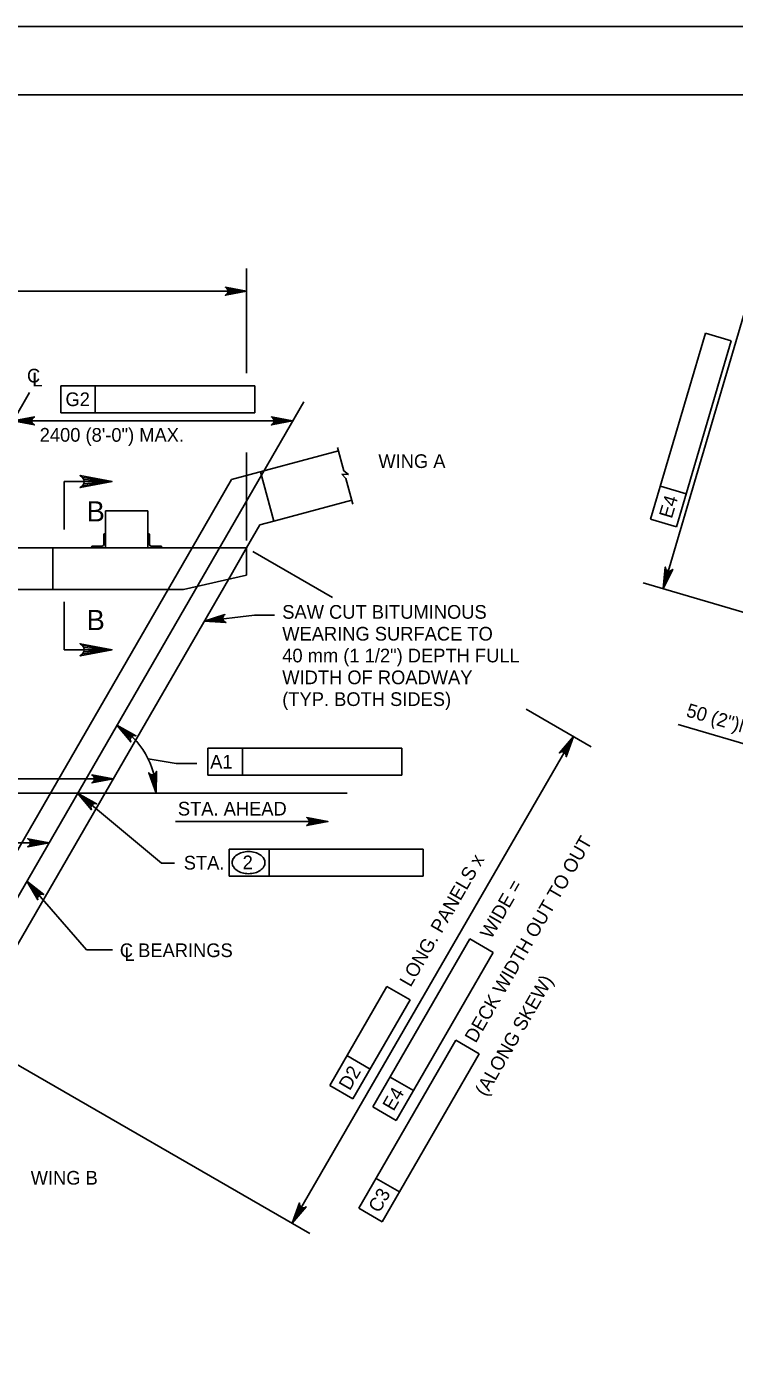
# Model space of a CAD drawing. Extents: x 638268 to 640277, y 295465 to 298435.
# Drawn here: x 639635.2 to 639790.3, y 298145.6 to 298435.5 of the extents above; entities that cross this region are included whole.
import ezdxf

# ---------------------------------------------------------------- set-up
doc = ezdxf.new("R2010")
doc.units = 0
for name, color, linetype in [('2', 7, 'Continuous'), ('3', 7, 'Continuous'), ('4', 7, 'Continuous'), ('PLT-BNDY', 7, 'Continuous')]:
    doc.layers.add(name, color=color, linetype=linetype)

msp = doc.modelspace()

# ---------------------------------------------------------------- linework, layer by layer
at = {"layer": '2'}
for p, q in [((639316.46, 298420.46), (640102.46, 298420.46)), ((639680.12, 298336.12), (639703.55, 298342.4)), ((639643.45, 298335.68), (639643.45, 298325.2)), ((639643.45, 298335.68), (639653.93, 298335.68)), ((639680.12, 298336.12), (639671.49, 298321.18)), ((639689.36, 298327.03), (639686.47, 298337.83)), ((639689.36, 298327.03), (639706.44, 298331.61)), ((639661.75, 298329.27), (639652.51, 298329.27)), ((639652.51, 298329.27), (639652.51, 298321.18)), ((639661.75, 298329.27), (639661.75, 298321.18)), ((639686.33, 298326.22), (639689.36, 298327.03)), ((639652.15, 298324.09), (639652.15, 298321.91)), ((639652.33, 298324.27), (639652.51, 298324.27)), ((639652.51, 298324.27), (639652.51, 298321.18)), ((639661.93, 298324.27), (639661.75, 298324.27)), ((639661.75, 298324.27), (639661.75, 298321.18)), ((639662.11, 298324.09), (639662.11, 298321.91)), ((639683.42, 298321.18), (639686.33, 298326.22)), ((639484.75, 298321.18), (639683.42, 298321.18)), ((639609.87, 298214.45), (639671.49, 298321.18)), ((639640.96, 298321.18), (639640.96, 298312.06)), ((639649.42, 298321.36), (639649.42, 298321.18)), ((639652.51, 298321.18), (639649.42, 298321.18)), ((639649.6, 298321.54), (639651.79, 298321.54)), ((639661.75, 298321.18), (639652.51, 298321.18)), ((639661.75, 298321.18), (639664.84, 298321.18)), ((639664.66, 298321.54), (639662.48, 298321.54)), ((639664.84, 298321.36), (639664.84, 298321.18)), ((639679.42, 298314.26), (639683.42, 298321.18)), ((639683.42, 298321.18), (639683.42, 298315.15)), ((639683.42, 298315.15), (639669.57, 298312.06)), ((639624.79, 298219.62), (639679.42, 298314.26)), ((639531.9, 298312.06), (639669.57, 298312.06)), ((639643.45, 298298.84), (639643.45, 298309.32)), ((639643.45, 298298.84), (639653.93, 298298.84))]:
    msp.add_line(p, q, dxfattribs=at)
for points in [[(639653.93, 298335.68), (639646.94, 298334.37), (639647.48, 298334.74), (639647.76, 298335.21), (639647.84, 298335.68), (639647.76, 298336.15), (639647.48, 298336.62), (639646.94, 298336.99), (639653.93, 298335.68), (639647.48, 298336.62), (639647.76, 298336.15), (639653.93, 298335.68), (639647.84, 298335.68), (639647.76, 298335.21), (639653.93, 298335.68), (639647.48, 298334.74)], [(639653.93, 298298.84), (639646.94, 298300.15), (639647.48, 298299.77), (639647.76, 298299.31), (639647.84, 298298.84), (639647.76, 298298.37), (639647.48, 298297.9), (639646.94, 298297.53), (639653.93, 298298.84), (639647.48, 298297.9), (639647.76, 298298.37), (639653.93, 298298.84), (639647.84, 298298.84), (639647.76, 298299.31), (639653.93, 298298.84), (639647.48, 298299.77)]]:
    msp.add_lwpolyline(points, dxfattribs=at)
for centre, radius, start, end in [((639652.33, 298324.09), 0.182, 90, 179.9984), ((639661.93, 298324.09), 0.182, 0.0016, 90), ((639649.6, 298321.36), 0.182, 90, 179.9984), ((639651.79, 298321.91), 0.364, 270, 359.9984), ((639662.48, 298321.91), 0.364, 180.0016, 270), ((639664.66, 298321.36), 0.182, 0.0016, 90)]:
    msp.add_arc(centre, radius, start, end, dxfattribs=at)
at = {"layer": '3'}
for p, q in [((639774.66, 298312.22), (639794.68, 298380.2)), ((639704.71, 298338.04), (639703.34, 298343.17)), ((639705.76, 298337.26), (639704.27, 298337.35)), ((639704.27, 298337.35), (639705.16, 298336.37)), ((639704.71, 298338.04), (639705.76, 298337.26)), ((639706.66, 298330.77), (639705.16, 298336.37)), ((639827.62, 298296.62), (639770.34, 298313.49))]:
    msp.add_line(p, q, dxfattribs=at)
msp.add_lwpolyline([(639775.02, 298315.24), (639775.98, 298314.96), (639774.66, 298312.22)], close=True, dxfattribs=at)
at = {"layer": '4'}
for p, q in [((639683.42, 298359.43), (639683.42, 298382.39)), ((639484.75, 298377.4), (639683.42, 298377.4)), ((639771.94, 298327.43), (639783.96, 298368.22)), ((639783.96, 298368.22), (639789.62, 298366.55)), ((639777.61, 298325.76), (639789.62, 298366.55)), ((639642.7, 298356.69), (639685.22, 298356.69)), ((639642.7, 298356.69), (639642.7, 298350.78)), ((639650.26, 298356.69), (639650.26, 298350.78)), ((639685.22, 298356.69), (639685.22, 298350.78)), ((639695.94, 298353.2), (639601.92, 298190.35)), ((639635.85, 298355.21), (639625.31, 298336.96)), ((639642.7, 298350.78), (639685.22, 298350.78)), ((639632.25, 298348.98), (639693.5, 298348.98)), ((639683.42, 298322.79), (639683.42, 298342.05)), ((639774.08, 298334.68), (639779.75, 298333.02)), ((639771.94, 298327.43), (639777.61, 298325.76)), ((639684.77, 298320.4), (639702.24, 298310.31)), ((639674.14, 298305.1), (639685.16, 298306.43)), ((639685.16, 298306.43), (639689.56, 298306.43)), ((639744.7, 298285.8), (639758.93, 298277.58)), ((639809.27, 298273.2), (639777.97, 298282.42)), ((639693.42, 298173.11), (639755.04, 298279.83)), ((639661.86, 298274.9), (639668, 298273.86)), ((639674.93, 298277.23), (639717.45, 298277.23)), ((639674.93, 298277.23), (639674.93, 298271.33)), ((639682.49, 298277.23), (639682.49, 298271.33)), ((639717.45, 298277.23), (639717.45, 298271.33)), ((639668, 298273.86), (639672.48, 298273.86)), ((639458.48, 298270.51), (639654.17, 298270.51)), ((639674.93, 298271.33), (639717.45, 298271.33)), ((639705.49, 298267.4), (639413.2, 298267.4)), ((639646.4, 298267.4), (639664.77, 298252.05)), ((639701.24, 298261.16), (639667.85, 298261.16)), ((639456.38, 298256.53), (639640.13, 298256.53)), ((639679.61, 298249.23), (639679.61, 298255.13)), ((639679.61, 298255.13), (639722.14, 298255.13)), ((639688.36, 298249.23), (639688.36, 298255.13)), ((639722.14, 298255.13), (639722.14, 298249.23)), ((639664.77, 298252.05), (639667.6, 298252.05)), ((639722.14, 298249.23), (639679.61, 298249.23)), ((639635.27, 298248.12), (639648.31, 298233.03)), ((639711.1, 298198.62), (639732.36, 298235.44)), ((639737.47, 298232.48), (639732.36, 298235.44)), ((639648.31, 298233.03), (639654.06, 298233.03)), ((639716.21, 298195.66), (639737.47, 298232.48)), ((639701.62, 298203.33), (639714.14, 298225.02)), ((639719.25, 298222.06), (639714.14, 298225.02)), ((639706.73, 298200.37), (639719.25, 298222.06)), ((639623.15, 298213.67), (639697.31, 298170.86)), ((639708.04, 298176.4), (639729.3, 298213.22)), ((639734.41, 298210.27), (639729.3, 298213.22)), ((639710.51, 298206.92), (639705.4, 298209.88)), ((639713.15, 298173.44), (639734.41, 298210.27)), ((639719.99, 298202.21), (639714.88, 298205.17)), ((639701.62, 298203.33), (639706.73, 298200.37)), ((639711.1, 298198.62), (639716.21, 298195.66)), ((639716.93, 298179.99), (639711.82, 298182.95)), ((639708.04, 298176.4), (639713.15, 298173.44))]:
    msp.add_line(p, q, dxfattribs=at)
for points in [[(639683.42, 298377.4), (639678.76, 298376.53), (639679.12, 298376.77), (639679.3, 298377.09), (639679.36, 298377.4), (639679.3, 298377.71), (639679.12, 298378.02), (639678.76, 298378.27), (639683.42, 298377.4), (639679.12, 298378.02), (639679.3, 298377.71), (639683.42, 298377.4), (639679.36, 298377.4), (639679.3, 298377.09), (639683.42, 298377.4), (639679.12, 298376.77)], [(639632.25, 298348.98), (639636.91, 298349.85), (639636.55, 298349.6), (639636.37, 298349.29), (639636.31, 298348.98), (639636.37, 298348.66), (639636.55, 298348.35), (639636.91, 298348.1), (639632.25, 298348.98), (639636.55, 298348.35), (639636.37, 298348.66), (639632.25, 298348.98), (639636.31, 298348.98), (639636.37, 298349.29), (639632.25, 298348.98), (639636.55, 298349.6)], [(639693.5, 298348.98), (639688.84, 298348.1), (639689.2, 298348.35), (639689.39, 298348.66), (639689.44, 298348.98), (639689.39, 298349.29), (639689.2, 298349.6), (639688.84, 298349.85), (639693.5, 298348.98), (639689.2, 298349.6), (639689.39, 298349.29), (639693.5, 298348.98), (639689.44, 298348.98), (639689.39, 298348.66), (639693.5, 298348.98), (639689.2, 298348.35)], [(639774.66, 298312.22), (639775.14, 298316.94), (639775.27, 298316.52), (639775.52, 298316.26), (639775.8, 298316.12), (639776.12, 298316.08), (639776.47, 298316.17), (639776.81, 298316.44), (639774.66, 298312.22), (639776.47, 298316.17), (639776.12, 298316.08), (639774.66, 298312.22), (639775.8, 298316.12), (639775.52, 298316.26), (639774.66, 298312.22), (639775.27, 298316.52)], [(639674.14, 298305.1), (639678.66, 298306.53), (639678.34, 298306.24), (639678.19, 298305.9), (639678.17, 298305.59), (639678.26, 298305.28), (639678.49, 298305), (639678.87, 298304.79), (639674.14, 298305.1), (639678.49, 298305), (639678.26, 298305.28), (639674.14, 298305.1), (639678.17, 298305.59), (639678.19, 298305.9), (639674.14, 298305.1), (639678.34, 298306.24)], [(639655, 298282.27), (639659.16, 298279.99), (639658.72, 298280.03), (639658.38, 298279.9), (639658.14, 298279.69), (639657.99, 298279.42), (639657.93, 298279.06), (639658.05, 298278.64), (639655, 298282.27), (639657.93, 298279.06), (639657.99, 298279.42), (639655, 298282.27), (639658.14, 298279.69), (639658.38, 298279.9), (639655, 298282.27), (639658.72, 298280.03)], [(639755.04, 298279.83), (639753.46, 298275.36), (639753.43, 298275.8), (639753.25, 298276.11), (639753, 298276.31), (639752.71, 298276.42), (639752.34, 298276.42), (639751.95, 298276.23), (639755.04, 298279.83), (639752.34, 298276.42), (639752.71, 298276.42), (639755.04, 298279.83), (639753, 298276.31), (639753.25, 298276.11), (639755.04, 298279.83), (639753.43, 298275.8)], [(639663.58, 298267.41), (639661.98, 298271.87), (639662.29, 298271.56), (639662.62, 298271.43), (639662.94, 298271.42), (639663.24, 298271.52), (639663.52, 298271.76), (639663.71, 298272.15), (639663.58, 298267.41), (639663.52, 298271.76), (639663.24, 298271.52), (639663.58, 298267.41), (639662.94, 298271.42), (639662.62, 298271.43), (639663.58, 298267.41), (639662.29, 298271.56)], [(639654.17, 298270.51), (639649.51, 298269.64), (639649.86, 298269.88), (639650.05, 298270.2), (639650.1, 298270.51), (639650.05, 298270.82), (639649.86, 298271.13), (639649.51, 298271.38), (639654.17, 298270.51), (639649.86, 298271.13), (639650.05, 298270.82), (639654.17, 298270.51), (639650.1, 298270.51), (639650.05, 298270.2), (639654.17, 298270.51), (639649.86, 298269.88)], [(639646.4, 298267.4), (639650.54, 298265.08), (639650.11, 298265.12), (639649.76, 298265), (639649.52, 298264.79), (639649.36, 298264.52), (639649.3, 298264.16), (639649.42, 298263.74), (639646.4, 298267.4), (639649.3, 298264.16), (639649.36, 298264.52), (639646.4, 298267.4), (639649.52, 298264.79), (639649.76, 298265), (639646.4, 298267.4), (639650.11, 298265.12)], [(639701.24, 298261.16), (639696.58, 298260.28), (639696.94, 298260.53), (639697.13, 298260.84), (639697.18, 298261.16), (639697.13, 298261.47), (639696.94, 298261.78), (639696.58, 298262.03), (639701.24, 298261.16), (639696.94, 298261.78), (639697.13, 298261.47), (639701.24, 298261.16), (639697.18, 298261.16), (639697.13, 298260.84), (639701.24, 298261.16), (639696.94, 298260.53)], [(639640.13, 298256.53), (639635.47, 298255.66), (639635.83, 298255.9), (639636.01, 298256.22), (639636.07, 298256.53), (639636.01, 298256.84), (639635.83, 298257.15), (639635.47, 298257.4), (639640.13, 298256.53), (639635.83, 298257.15), (639636.01, 298256.84), (639640.13, 298256.53), (639636.07, 298256.53), (639636.01, 298256.22), (639640.13, 298256.53), (639635.83, 298255.9)], [(639635.27, 298248.12), (639638.98, 298245.16), (639638.56, 298245.27), (639638.2, 298245.21), (639637.93, 298245.05), (639637.73, 298244.8), (639637.61, 298244.46), (639637.66, 298244.02), (639635.27, 298248.12), (639637.61, 298244.46), (639637.73, 298244.8), (639635.27, 298248.12), (639637.93, 298245.05), (639638.2, 298245.21), (639635.27, 298248.12), (639638.56, 298245.27)], [(639693.42, 298173.11), (639694.99, 298177.58), (639695.02, 298177.14), (639695.2, 298176.83), (639695.45, 298176.62), (639695.75, 298176.51), (639696.11, 298176.52), (639696.5, 298176.71), (639693.42, 298173.11), (639696.11, 298176.52), (639695.75, 298176.51), (639693.42, 298173.11), (639695.45, 298176.62), (639695.2, 298176.83), (639693.42, 298173.11), (639695.02, 298177.14)]]:
    msp.add_lwpolyline(points, dxfattribs=at)
for points in [[(639690.67, 298349.45), (639690.67, 298348.5), (639693.5, 298348.98)], [(639677.01, 298304.97), (639676.9, 298305.91), (639674.14, 298305.1)], [(639753.1, 298277.48), (639753.97, 298276.98), (639755.04, 298279.83)], [(639694.48, 298175.95), (639695.35, 298175.45), (639693.42, 298173.11)]]:
    msp.add_lwpolyline(points, close=True, dxfattribs=at)
for centre, radius, start, end in [((639646.4, 298267.4), 17.18, 0.0029, 59.9982), ((639683.46, 298250.73), 3.82, 105.6708, 124.109), ((639683.85, 298249.33), 5.27, 90, 105.6708), ((639683.85, 298249.33), 5.27, 74.3292, 90), ((639684.24, 298250.73), 3.82, 55.891, 74.3292), ((639681.94, 298252.17), 1.68, 148.5507, 180), ((639681.94, 298252.17), 1.68, 180, 211.4493), ((639682.86, 298251.61), 2.75, 124.109, 148.5507), ((639684.84, 298251.61), 2.75, 31.4493, 55.891), ((639685.76, 298252.17), 1.68, 0, 31.4493), ((639685.76, 298252.17), 1.68, 328.5507, 0), ((639682.86, 298252.73), 2.75, 211.4493, 235.891), ((639683.46, 298253.61), 3.82, 235.891, 254.3292), ((639683.85, 298255.01), 5.27, 254.3292, 270), ((639683.85, 298255.01), 5.27, 270, 285.6708), ((639684.24, 298253.61), 3.82, 285.6708, 304.109), ((639684.84, 298252.73), 2.75, 304.109, 328.5507)]:
    msp.add_arc(centre, radius, start, end, dxfattribs=at)
at = {"layer": 'PLT-BNDY'}
msp.add_lwpolyline([(639276.46, 298435.46), (640117.46, 298435.46), (640117.46, 297841.46), (639276.46, 297841.46)], close=True, dxfattribs=at)

# ---------------------------------------------------------------- texts
at = {"layer": '4'}
for s, height, p in [('C', 3, (639635.3, 298357.41)), ('L', 3, (639636.46, 298356.54)), ('WING A', 3, (639712.29, 298338.67)), ('B', 4.43, (639648.39, 298303.13)), ('SAW CUT BITUMINOUS', 3, (639691.23, 298305.62)), ('WEARING SURFACE TO', 3, (639691.23, 298300.84)), ('40 mm (1 1/2") DEPTH FULL', 3, (639691.23, 298296.06)), ('WIDTH OF ROADWAY', 3, (639691.23, 298291.28)), ('(TYP. BOTH SIDES)', 3, (639691.23, 298286.5)), ('STA. AHEAD', 3, (639668.36, 298262.49)), ('STA.', 3, (639669.65, 298250.65)), ('2', 3, (639682.55, 298250.71)), ('C BEARINGS', 3, (639655.64, 298231.45)), ('L', 3, (639656.63, 298230.61)), ('WING B', 3, (639636.11, 298181.58))]:
    msp.add_text(s, height=height, dxfattribs=at).set_placement(p)
for s, height, rotation, p in [('G2', 3, 359.9382, (639643.73, 298352.23)), ('2400 (8\'-0") MAX.', 3, 359.9382, (639638.08, 298344.44)), ('E4', 3, 73.5262, (639776.59, 298327.43)), ('B', 4.43, 360, (639648.39, 298326.95)), ('50 (2")MIN.', 3, 343.588, (639779.54, 298284.27)), ('A1', 3, 359.9382, (639675.44, 298272.78)), ('DECK WIDTH OUT TO OUT', 3, 60, (639733.62, 298212.45)), ('LONG. PANELS x', 3, 60, (639719.34, 298224.71)), ('WIDE =', 3, 60, (639737.01, 298235.23)), ('(ALONG SKEW)', 3, 60, (639735.89, 298200.72)), ('D2', 3, 59.9382, (639706.02, 298202.03)), ('E4', 3, 59.9382, (639715.61, 298197.53)), ('C3', 3, 59.9382, (639712.49, 298175.21))]:
    msp.add_text(s, height=height, rotation=rotation, dxfattribs=at).set_placement(p)

doc.saveas('drawing.dxf')
